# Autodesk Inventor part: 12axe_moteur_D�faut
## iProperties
Created: 2011-01
Part Number: 12axe_moteur_D�faut
Document SubType Name: Modeling
Designer: eric
Density: 1 g/cm^3
Mass: 0.926695 g
Surface Area: 5.91591 cm^2
Volume: 0.926695 cm^3
Author: eric
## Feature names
1. Base1
